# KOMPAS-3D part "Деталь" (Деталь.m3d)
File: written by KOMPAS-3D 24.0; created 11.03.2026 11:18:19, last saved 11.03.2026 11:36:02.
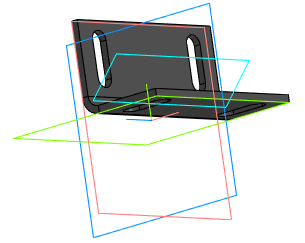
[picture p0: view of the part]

Document properties: Автор: R2D2; Полное имя файла: E:\Работа\Зайцев\БКВ APL-210N Блок концевых выключателей DN.ru\исходные материалы\Деталь.m3d

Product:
- Part/product: Деталь
    Масса: 0.031984

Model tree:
1. Эскиз:1
2. Листовое тело:1
     Расстояние 1 = 50; Радиус сгиба = 3; Коэффициент = 0.4; Величина сгиба = 10
3. Эскиз:2  (with: Грань.Листовое тело:1)
4. Вырез в листовом теле:1
     Глубина выреза = 10
5. Средняя плоскость:1  (with: Грань.Листовое тело:1)
6. Зеркальный массив:1
7. Экземпляр ( 1 )
8. Экземпляр ( 2 )  (with: Вырез в листовом теле:1)

Expressions: v76/2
